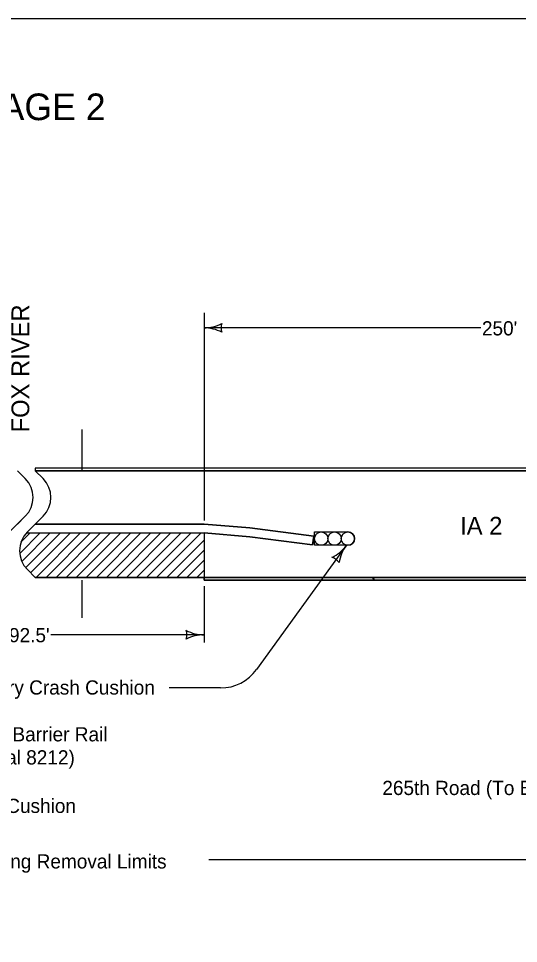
# Model space of a CAD drawing. Extents: x -2134934 to -2119606, y -2139046 to -2137036.
# Drawn here: x -2128679 to -2128116, y -2138077 to -2137036 of the extents above; entities that cross this region are included whole.
import ezdxf

# ---------------------------------------------------------------- set-up
doc = ezdxf.new("R2010")
doc.units = 0
for name, color, linetype in [('Default', 7, 'Continuous'), ('dsnCellElements', 7, 'Continuous'), ('dsnCellsNorthArrow', 7, 'Continuous'), ('dsnStdLabel', 7, 'Continuous'), ('dsnStdLineWork', 7, 'Continuous'), ('Level 2', 7, 'Continuous')]:
    doc.layers.add(name, color=color, linetype=linetype)

msp = doc.modelspace()

# ---------------------------------------------------------------- linework, layer by layer
at = {"layer": 'Default'}
msp.add_lwpolyline([(-2130232, -2137035.9), (-2127097, -2137035.9), (-2127097, -2139045.9), (-2130232, -2139045.9)], close=True, dxfattribs=at)
at = {"layer": 'dsnCellElements'}
for centre, radius, start, end in [((-2128470.1, -2137341.8), 42.5, 270, 298.0725), ((-2128470.1, -2137426.8), 42.5, 61.9275, 90), ((-2128434.5, -2137384.3), 16.4, 162.2666, 197.7334), ((-2128344.4, -2137604.4), 42.5, 295.6285, 323.701), ((-2128275.9, -2137654.7), 42.5, 143.701, 171.7735), ((-2128331.3, -2137658.2), 16.4, 35.9676, 71.4343)]:
    msp.add_arc(centre, radius, start, end, dxfattribs=at)
at = {"layer": 'dsnStdLineWork'}
for p, q in [((-2127160.1, -2137542.2), (-2128660.1, -2137542.2)), ((-2127160.1, -2137542.2), (-2128660.1, -2137542.2)), ((-2128660.1, -2137542.2), (-2128660.1, -2137545.2)), ((-2127160.1, -2137545.2), (-2128660.1, -2137545.2)), ((-2128660.1, -2137545.2), (-2127810.1, -2137545.2)), ((-2128660.1, -2137665.2), (-2127159.5, -2137665.2)), ((-2128470.1, -2137665.2), (-2128470.1, -2137668.2)), ((-2128470.1, -2137668.2), (-2128470.1, -2137665.2)), ((-2128278.1, -2137668.2), (-2128280.3, -2137665.2)), ((-2128280.3, -2137665.2), (-2128278.1, -2137668.2)), ((-2127805.1, -2137665.2), (-2128280.3, -2137665.2)), ((-2128470.1, -2137668.2), (-2128278.1, -2137668.2)), ((-2128278.1, -2137668.2), (-2127805.1, -2137668.2))]:
    msp.add_line(p, q, dxfattribs=at)
for points in [[(-2128471.3, -2137545.2), (-2127158.8, -2137545.2)], [(-2127160.1, -2137665.2), (-2128470.1, -2137665.2)], [(-2128280.3, -2137665.2), (-2128469.7, -2137665.2), (-2128470.1, -2137665.2)], [(-2127160.1, -2137668.2), (-2128470.1, -2137668.2)]]:
    msp.add_lwpolyline(points, dxfattribs=at)
at = {"layer": 'Level 2'}
for p, q in [((-2128470.1, -2137367.2), (-2128470.1, -2137601.1)), ((-2128158.6, -2137384.3), (-2128470.1, -2137384.3)), ((-2128607.6, -2137498.8), (-2128607.6, -2137545.2)), ((-2128680.1, -2137545.2), (-2128671.3, -2137553.9)), ((-2128671.3, -2137553.9), (-2128680.1, -2137545.2)), ((-2128660.1, -2137545.2), (-2128651.3, -2137553.9)), ((-2127160.1, -2137545.2), (-2128660.1, -2137545.2)), ((-2128660.1, -2137545.2), (-2128651.3, -2137553.9)), ((-2128671.3, -2137596.4), (-2128688.9, -2137613.9)), ((-2128651.3, -2137596.4), (-2128668.9, -2137613.9)), ((-2128651.3, -2137596.4), (-2128660.1, -2137605.2)), ((-2128660.1, -2137605.2), (-2128668.9, -2137613.9)), ((-2128470.1, -2137605.2), (-2128660.1, -2137605.2)), ((-2128470.1, -2137605.2), (-2128660.1, -2137605.2)), ((-2128660.1, -2137605.2), (-2128470.1, -2137605.2)), ((-2128660.1, -2137605.2), (-2128470.1, -2137605.2)), ((-2128418.6, -2137609.5), (-2128470.1, -2137605.2)), ((-2128470.1, -2137605.2), (-2128418.6, -2137609.5)), ((-2128470.1, -2137605.2), (-2128418.6, -2137609.5)), ((-2128346.6, -2137618.8), (-2128418.6, -2137609.5)), ((-2128346.6, -2137618.8), (-2128418.6, -2137609.5)), ((-2128418.6, -2137609.5), (-2128346.6, -2137618.8)), ((-2128418.6, -2137609.5), (-2128346.6, -2137618.8)), ((-2128345.6, -2137629.1), (-2128345.6, -2137614.1)), ((-2128345.6, -2137614.1), (-2128308.1, -2137614.1)), ((-2128345.6, -2137629.1), (-2128345.6, -2137614.1)), ((-2128345.6, -2137614.1), (-2128308.1, -2137614.1)), ((-2128654.4, -2137615.2), (-2128677.5, -2137638.3)), ((-2128665.7, -2137615.2), (-2128676.1, -2137625.6)), ((-2128643.1, -2137615.2), (-2128675.1, -2137647.2)), ((-2128631.8, -2137615.2), (-2128670.8, -2137654.2)), ((-2128670.1, -2137615.2), (-2128470.5, -2137615.2)), ((-2128670.1, -2137615.2), (-2128470.1, -2137615.2)), ((-2128620.4, -2137615.2), (-2128665.3, -2137660)), ((-2128609.1, -2137615.2), (-2128659.1, -2137665.2)), ((-2128597.8, -2137615.2), (-2128647.8, -2137665.2)), ((-2128586.5, -2137615.2), (-2128636.5, -2137665.2)), ((-2128575.2, -2137615.2), (-2128625.2, -2137665.2)), ((-2128563.9, -2137615.2), (-2128613.9, -2137665.2)), ((-2128552.6, -2137615.2), (-2128602.6, -2137665.2)), ((-2128591.2, -2137665.2), (-2128541.2, -2137615.2)), ((-2128529.9, -2137615.2), (-2128579.9, -2137665.2)), ((-2128518.6, -2137615.2), (-2128568.6, -2137665.2)), ((-2128507.3, -2137615.2), (-2128557.3, -2137665.2)), ((-2128496, -2137615.2), (-2128546, -2137665.2)), ((-2128484.7, -2137615.2), (-2128534.7, -2137665.2)), ((-2128473.4, -2137615.2), (-2128523.4, -2137665.2)), ((-2128470.1, -2137623.2), (-2128512.1, -2137665.2)), ((-2128470.5, -2137615.2), (-2128470.4, -2137615.2)), ((-2128470.4, -2137615.2), (-2128470.1, -2137615.2)), ((-2128470.1, -2137615.2), (-2128470.1, -2137665.2)), ((-2128470.1, -2137615.2), (-2128470.1, -2137615.2)), ((-2128470.1, -2137615.2), (-2128418.4, -2137619.5)), ((-2128470.1, -2137615.2), (-2128418.4, -2137619.5)), ((-2128418.4, -2137619.5), (-2128470.1, -2137615.2)), ((-2128470.1, -2137615.2), (-2128470.1, -2137665.2)), ((-2128418.4, -2137619.5), (-2128347.9, -2137628.7)), ((-2128418.4, -2137619.5), (-2128347.9, -2137628.7)), ((-2128347.9, -2137628.7), (-2128418.4, -2137619.5)), ((-2128347.9, -2137628.7), (-2128346.6, -2137618.8)), ((-2128346.6, -2137618.8), (-2128347.9, -2137628.7)), ((-2128346.6, -2137618.8), (-2128347.9, -2137628.7)), ((-2128470.1, -2137634.5), (-2128500.8, -2137665.2)), ((-2128310.2, -2137629.5), (-2128411, -2137769)), ((-2128308.1, -2137629.1), (-2128345.6, -2137629.1)), ((-2128308.1, -2137629.1), (-2128345.6, -2137629.1)), ((-2128470.1, -2137645.8), (-2128489.5, -2137665.2)), ((-2128668.9, -2137656.4), (-2128660.1, -2137665.2)), ((-2128470.1, -2137657.1), (-2128478.2, -2137665.2)), ((-2128470.1, -2137665.2), (-2127160.1, -2137665.2)), ((-2128607.6, -2137668.2), (-2128607.6, -2137710.9)), ((-2128470.1, -2137675.2), (-2128470.1, -2137738.5)), ((-2128470.1, -2137729.8), (-2128642.4, -2137729.8)), ((-2128451.5, -2137789.7), (-2128509.3, -2137789.7)), ((-2127805.1, -2137983.3), (-2128464.5, -2137983.3))]:
    msp.add_line(p, q, dxfattribs=at)
for points in [[(-2128680.1, -2137605.2), (-2128680.1, -2137605.2), (-2128671.3, -2137596.4)], [(-2128660.1, -2137605.2), (-2128660.1, -2137605.2)], [(-2128660.1, -2137605.2), (-2128660.1, -2137605.2)], [(-2128308.1, -2137614.1), (-2128308.1, -2137614.1)], [(-2128470.5, -2137615.2), (-2128470.5, -2137615.2)], [(-2128308.1, -2137629.1), (-2128308.1, -2137629.1)], [(-2128470.1, -2137665.2), (-2128660.1, -2137665.2)]]:
    msp.add_lwpolyline(points, dxfattribs=at)
for centre in [(-2128338.1, -2137621.6), (-2128338.1, -2137621.6), (-2128323.1, -2137621.6), (-2128323.1, -2137621.6), (-2128308.1, -2137621.6), (-2128308.1, -2137621.6)]:
    msp.add_circle(centre, 7.5, dxfattribs=at)
for centre, radius, start, end in [((-2128692.5, -2137575.2), 30, 315, 45), ((-2128692.5, -2137575.2), 30, 315, 45), ((-2128672.5, -2137575.2), 30, 315, 45), ((-2128672.5, -2137575.2), 30, 315, 45), ((-2128647.7, -2137635.2), 30, 135, 225), ((-2128647.7, -2137635.2), 30, 135, 138.1884), ((-2128308.1, -2137621.6), 7.5, 270.0028, 89.9972), ((-2128505.8, -2137729.8), 16.4, 342.2666, 17.7334), ((-2128470.1, -2137687.4), 42.5, 241.9275, 270), ((-2128470.1, -2137772.3), 42.5, 90, 118.0725), ((-2128451.5, -2137739.7), 50, 270, 324.138)]:
    msp.add_arc(centre, radius, start, end, dxfattribs=at)

# ---------------------------------------------------------------- texts
at = {"layer": 'dsnCellsNorthArrow'}
msp.add_text('FOX RIVER', height=20, rotation=90, dxfattribs=at).set_placement((-2128666.8, -2137502))
msp.add_text('IA 2', height=20, dxfattribs=at).set_placement((-2128181.8, -2137617.1))
at = {"layer": 'dsnStdLabel'}
msp.add_text('STAGE 2', height=30, dxfattribs=at).set_placement((-2128750.3, -2137150.4))
at = {"layer": 'Level 2'}
for s, p in [("250'", (-2128157.3, -2137392.8)), ("392.5'", (-2128701.5, -2137738.3)), ('Temporary Crash Cushion', (-2128776.3, -2137797.2)), ('Temporary Barrier Rail', (-2128795.1, -2137849.9)), ('(See Typical 8212)', (-2128795.1, -2137875.9)), ('265th Road (To Be Closed)', (-2128269.4, -2137910.3)), ('Temporary Crash Cushion', (-2128865.1, -2137930.5)), ('Pavement Marking Removal Limits', (-2128842.8, -2137993))]:
    msp.add_text(s, height=16, dxfattribs=at).set_placement(p)

doc.saveas('drawing.dxf')
